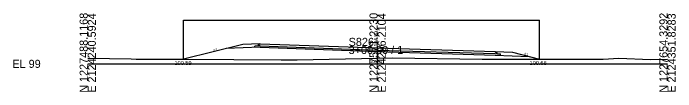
# Model space of a CAD drawing. Extents: x 2118382 to 2118616, y 1213030 to 1222057.
# Drawn here: x 2118381.9 to 2118610.4, y 1213530.1 to 1213557.3 of the extents above; entities that cross this region are included whole.
import ezdxf

# ---------------------------------------------------------------- set-up
doc = ezdxf.new("R2010")
doc.units = 0
for name, color, linetype in [('XS_CELL', 7, 'Continuous'), ('XS_M_DITCH', 7, 'Continuous'), ('XS_P_FINISHED_GRADE', 7, 'Continuous'), ('XS_P_FINISHED_GRADE_ELEV_TX', 7, 'Continuous'), ('XS_P_SUBGRADE_GRANULAR', 7, 'Continuous'), ('XS_P_SUBGRADE_PAVEMENT', 7, 'Continuous'), ('XS_P_TX_DCH', 7, 'Continuous'), ('XS_P_TX_FS_BS', 7, 'Continuous'), ('XS_X_GROUND', 7, 'Continuous'), ('XS_X_GROUND_TX', 7, 'Continuous')]:
    doc.layers.add(name, color=color, linetype=linetype)

msp = doc.modelspace()

# ---------------------------------------------------------------- linework, layer by layer
at = {"layer": 'XS_CELL'}
for p, q in [((2118507.6, 1213539.8), (2118507.6, 1213546)), ((2118407.6, 1213539.8), (2118507.6, 1213539.8)), ((2118507.6, 1213539.8), (2118607.6, 1213539.8))]:
    msp.add_line(p, q, dxfattribs=at)
at = {"layer": 'XS_M_DITCH'}
for p, q in [((2118440.64, 1213541.39), (2118440.64, 1213554.96)), ((2118440.64, 1213554.96), (2118563.5, 1213554.96)), ((2118563.5, 1213541.46), (2118563.5, 1213554.96))]:
    msp.add_line(p, q, dxfattribs=at)
at = {"layer": 'XS_P_FINISHED_GRADE'}
for p, q in [((2118461.08, 1213546.5), (2118440.64, 1213541.39)), ((2118467.08, 1213546.74), (2118461.08, 1213546.5)), ((2118467.08, 1213546.74), (2118507.6, 1213545.3)), ((2118507.6, 1213545.3), (2118548.16, 1213544.04)), ((2118548.16, 1213544.04), (2118554.16, 1213543.8)), ((2118554.16, 1213543.8), (2118563.5, 1213541.46))]:
    msp.add_line(p, q, dxfattribs=at)
at = {"layer": 'XS_P_SUBGRADE_GRANULAR'}
for p, q in [((2118467.08, 1213545.54), (2118455.33, 1213545.07)), ((2118466.24, 1213546), (2118465.24, 1213545.96)), ((2118465.24, 1213545.46), (2118465.24, 1213545.96)), ((2118467.08, 1213545.54), (2118507.56, 1213544.09)), ((2118507.56, 1213544.09), (2118548.16, 1213542.83)), ((2118548.16, 1213542.83), (2118559.92, 1213542.36)), ((2118549.01, 1213543.29), (2118550.01, 1213543.25)), ((2118550.01, 1213542.75), (2118550.01, 1213543.25))]:
    msp.add_line(p, q, dxfattribs=at)
at = {"layer": 'XS_P_SUBGRADE_PAVEMENT'}
for p, q in [((2118466.39, 1213546.26), (2118466.24, 1213546)), ((2118467.08, 1213546.04), (2118466.24, 1213546)), ((2118467.08, 1213546.74), (2118466.39, 1213546.26)), ((2118467.08, 1213546.04), (2118507.58, 1213544.59)), ((2118507.58, 1213544.59), (2118548.16, 1213543.33)), ((2118548.16, 1213544.04), (2118548.86, 1213543.55)), ((2118548.16, 1213543.33), (2118549.01, 1213543.29)), ((2118548.86, 1213543.55), (2118549.01, 1213543.29))]:
    msp.add_line(p, q, dxfattribs=at)
at = {"layer": 'XS_X_GROUND'}
for p, q in [((2118407.6, 1213541.76), (2118422.59, 1213541.56)), ((2118422.59, 1213541.56), (2118424.3, 1213541.42)), ((2118424.3, 1213541.42), (2118428.37, 1213541.43)), ((2118428.37, 1213541.43), (2118441.67, 1213541.39)), ((2118441.67, 1213541.39), (2118474.37, 1213541.22)), ((2118474.37, 1213541.22), (2118479.89, 1213541.24)), ((2118479.89, 1213541.24), (2118507.6, 1213541.77)), ((2118507.6, 1213541.77), (2118512.72, 1213541.87)), ((2118512.72, 1213541.87), (2118543.67, 1213541.39)), ((2118543.67, 1213541.39), (2118552.55, 1213541.39)), ((2118552.55, 1213541.39), (2118564.69, 1213541.47)), ((2118564.69, 1213541.47), (2118585.36, 1213541.37)), ((2118585.36, 1213541.37), (2118590.78, 1213541.82)), ((2118590.78, 1213541.82), (2118601.73, 1213541.33)), ((2118601.73, 1213541.33), (2118607.6, 1213541.43))]:
    msp.add_line(p, q, dxfattribs=at)

# ---------------------------------------------------------------- texts
at = {"layer": 'XS_CELL'}
for s, p in [('N 1227488.1168', (2118407.6, 1213529.8)), ('E 2124240.5924', (2118410.4, 1213529.8)), ('N 1227571.2230', (2118507.6, 1213529.8)), ('E 2124296.2104', (2118510.4, 1213529.8)), ('N 1227654.3292', (2118607.6, 1213529.8)), ('E 2124351.8283', (2118610.4, 1213529.8))]:
    msp.add_text(s, height=2.8, rotation=90, dxfattribs=at).set_placement(p)
for s, p in [('S826', (2118497.6, 1213546)), ('3+00.00 / 1', (2118497.6, 1213543.2)), ('EL 99', (2118381.6, 1213538.4))]:
    msp.add_text(s, height=2.8, dxfattribs=at).set_placement(p)
at = {"layer": 'XS_P_FINISHED_GRADE_ELEV_TX'}
msp.add_text(' 104.50', height=1.25, rotation=90, dxfattribs=at).set_placement((2118507.6, 1213545.34))
at = {"layer": 'XS_P_TX_DCH'}
for s, p in [('100.59', (2118437.51, 1213539.39)), ('100.66', (2118560.01, 1213539.39))]:
    msp.add_text(s, height=1.4, dxfattribs=at).set_placement(p)
at = {"layer": 'XS_P_TX_FS_BS'}
for rotation, p in [(14.0362, (2118450.94, 1213544.11)), (14.0362, (2118450.94, 1213544.11)), (345.9638, (2118558.06, 1213542.96))]:
    msp.add_text('4:1', height=0.8, rotation=rotation, dxfattribs=at).set_placement(p)
at = {"layer": 'XS_X_GROUND_TX'}
msp.add_text('100.97', height=1, dxfattribs=at).set_placement((2118504.95, 1213540.04))

doc.saveas('drawing.dxf')
